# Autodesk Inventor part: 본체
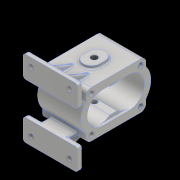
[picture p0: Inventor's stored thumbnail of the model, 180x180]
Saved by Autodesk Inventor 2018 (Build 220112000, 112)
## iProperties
Created: 2023-06
Part Number: 본체
Material: 알루미늄 6061
Document SubType Name: Modeling
Designer: home
Density: 2.7 g/cm^3
Appearance: 알루미늄 - 평지
Mass: 1268.05 g
Surface Area: 985.393 cm^2
Volume: 469.65 cm^3
Author: home
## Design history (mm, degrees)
sketch "스케치1"
  geometry: L1 (-50, 70)-(50, 70); L2 (50, -70)-(-50, -70); L3 (-50, 70)-(50, -70); L4 (50, 70)-(-50, -70); L5 (50, -30)-(-50, -30); L6 (50, 30)-(-50, 30); L7 (50, 70)-(50, 30); L8 (50, -30)-(50, -70); L9 (-50, -70)-(-50, -30); L10 (-50, 30)-(-50, 70); 1 further point
  constraints: 20 end point, 5 parallel, 3 horizontal, 2 midpoint, 2 perpendicular
  dimensions: "d0" = 100 distance of L2.start L2.end; "d1" = 140 distance of L1.end L2.start; "d2" = 40 distance between parallel lines of L1 L6; "d3" = 40 distance between parallel lines of L2 L5; "d4" = 35.5377 deg angle of L7 L3; "d5" = 35.5377 deg angle of L7 L4
extrude "돌출1" new body sketch "스케치1" distance "d6" = 9; taper "d7" = 0 deg
sketch "스케치2"
  geometry: L1 (25, 42.5)-(135, 42.5); L2 (135, 42.5)-(135, -42.5); L3 (135, -42.5)-(25, -42.5); L4 (25, -42.5)-(25, 42.5); L5 (25, 42.5)-(135, -42.5); L6 (135, 42.5)-(25, -42.5); L7 (86.507, 22.5)-(73.493, 22.5); L8 (86.507, -22.5)-(73.493, -22.5); A1 r 40 centre (56, 0) between (25, 25.278) and (25, -25.278); A2 r 40 centre (104, 0) between (135, -25.278) and (135, 25.278); A3 r 28.5 centre (56, 0) between (73.493, 22.5) and (73.493, -22.5); A4 r 28.5 centre (104, 0) between (86.507, -22.5) and (86.507, 22.5); 4 further points
  constraints: 16 end point, 8 point on circle, 4 centre point, 4 midpoint, 4 point on line, 3 horizontal, 2 coincident, 2 equal radius, 2 horizontal alignment, 2 parallel, 1 perpendicular
  dimensions: "d8" = 110 distance of L2.end L3.end; "d9" = 85 distance of L1.end L2.end; "d10" = 80 distance of point (0, 0) point (80, 0); "d17" = 31 distance from line of L4 A1.centre; "d20" = 22.5 distance from line of point (80, 0) L8; "d21" = 22.5 distance from line of point (80, 0) L7; "d119" = 28.5 radius of A4; "d121" = 61.50714 distance from line of L7.end L2; "d122" = 48 distance of A1.centre A2.centre; "d124" = 40 radius of A2
extrude "돌출2" join sketch "스케치2" stored distance "d25" = 79; taper "d26" = 0 deg
fillet "모깎기1" dims "d30" = 5
sketch "스케치4"
  geometry: L1 (-50, -35)-(-50, -65) reference; L2 (-45, -70)-(45, -70) reference; L3 (50, -65)-(50, -35) reference; L4 (45, -30)-(-45, -30) reference; C1 r 9 at (-35, -55); C2 r 9 at (35, -55); C3 r 9 at (-35, 55); C4 r 9 at (35, 55); A1 r 5 centre (-45, -35) between (-45, -30) and (-50, -35) reference; A2 r 5 centre (-45, -65) between (-50, -65) and (-45, -70) reference; A3 r 5 centre (45, -65) between (45, -70) and (50, -65) reference; A4 r 5 centre (45, -35) between (50, -35) and (45, -30) reference; 1 further point
  constraints: 4 centre point, 2 vertical alignment, 1 horizontal alignment
  dimensions: "d31" = 18 diameter of C1; "d32" = 18 diameter of C2; "d33" = 70 distance of C2.centre C1.centre; "d34" = 18 diameter of C3; "d35" = 18 diameter of C4; "d36" = 55 vertical distance of point (0, 0) C1.centre; "d37" = 55 vertical distance of C3.centre point (0, 0); "d38" = 35 horizontal distance of C2.centre point (0, 0); "d39" = 55 vertical distance of point (0, 0) C4.centre
extrude "돌출3" join sketch "스케치4" distance "d40" = 3; taper "d41" = 0 deg
sketch "스케치6"
  geometry: C1 r 9 at (0, 0) reference; C2 r 9 at (70, 0) reference; C3 r 9 at (70, 110) reference; C4 r 9 at (0, 110) reference; 1 further point
hole "구멍1" sketch "스케치6" at (0, 0), (70, 0), (70, 110), (0, 110) diameter "d42" = 9; stored, may be unused: countersink angle "d46" = 90 deg, drill point angle "d48" = 118 deg; dims "d43" = 6, "d44" = 4, "d45" = 2, "d47" = 8
sketch "스케치7"
  geometry: L1 (9, 30)-(25, 30); L2 (25, 38)-(9, 38); L3 (25, 25.278)-(25, 42.5) reference; L4 (25, 38)-(25, 30); L5 (9, 38)-(9, 30); L6 (9, -30)-(9, -35) reference; L7 (9, -30)-(25, -30); L8 (25, -42.5)-(25, -25.278) reference; L9 (25, -38)-(9, -38); L10 (9, -65)-(9, -35) reference; L11 (25, -30)-(25, -38); L12 (9, -30)-(9, -38); 1 further point
  constraints: 16 end point, 5 point on line, 4 horizontal, 1 collinear, 1 perpendicular, 1 vertical
  dimensions: "d49" = 8 distance between parallel lines of L1 L2; "d52" = 8 distance between parallel lines of L9 L7
extrude "돌출4" join sketch "스케치7" stored distance "d50" = 50; taper "d51" = 0 deg
node "작업 평면1"
sketch "스케치8"
  geometry: L1 (9, 62)-(54.939, 42.5); L2 (0, 70)-(9, 70) reference; L3 (9, 64)-(9, 46) reference; L4 (25, 42.5)-(135, 42.5) reference; 1 further point
  constraints: 2 end point, 2 point on line
  dimensions: "d54" = 8 distance from line of L2 L1.start; "d55" = 23 deg angle of L2 L1
feature "리브1" sketch "스케치8" dims "d56" = 1, "d57" = 7, "d58" = 0, "d59" = 0, "d60" = 1, "d61" = 1
fillet "모깎기2" dims "d62" = 10
sketch "스케치9"
  geometry: L1 (22.5, 86.507)-(22.5, 73.493) reference; L2 (-22.5, 73.493)-(-22.5, 86.507) reference; L3 (42.5, 35)-(42.5, 125) reference; L4 (32.5, 135)-(25.278, 135) reference; L5 (-25.278, 135)-(-32.5, 135) reference; L6 (-42.5, 125)-(-42.5, 35) reference; L7 (-32.5, 25)-(-25.278, 25) reference; L8 (25.278, 25)-(32.5, 25) reference; A1 r 28.5 centre (0, 104) between (22.5, 86.507) and (-22.5, 86.507) reference; A2 r 28.5 centre (0, 56) between (-22.5, 73.493) and (22.5, 73.493) reference; A3 r 10 centre (32.5, 35) between (32.5, 25) and (42.5, 35) reference; A4 r 10 centre (32.5, 125) between (42.5, 125) and (32.5, 135) reference; A5 r 40 centre (0, 104) between (25.278, 135) and (-25.278, 135) reference; A6 r 10 centre (-32.5, 125) between (-32.5, 135) and (-42.5, 125) reference; A7 r 10 centre (-32.5, 35) between (-42.5, 35) and (-32.5, 25) reference; A8 r 40 centre (0, 56) between (-25.278, 25) and (25.278, 25) reference; 1 further point
hole "구멍2" sketch "스케치9" at (-32.5, 125), (32.5, 125), (32.5, 35), (-32.5, 35) diameter "d63" = 9; stored, may be unused: countersink angle "d67" = 90 deg, drill point angle "d69" = 118 deg; dims "d64" = 6, "d65" = 4, "d66" = 2, "d68" = 8
sketch "스케치10"
  geometry: L1 (63, -54.939)-(-27, -54.939) reference; L2 (3, 30.061)-(3, 20.061); L3 (33, 20.061)-(33, 30.061); A1 r 15 centre (18, 30.061) between (33, 30.061) and (3, 30.061); A2 r 15 centre (18, 20.061) between (3, 20.061) and (33, 20.061); 1 further point
  constraints: 4 end point, 4 point on circle, 4 tangent, 2 centre point, 1 vertical
  dimensions: "d73" = 30 diameter of A1; "d74" = 30 diameter of A2; "d75" = 30 distance from line of L1.start L3; "d76" = 85 distance from line of L3.end L1; "d77" = 75 distance from line of L3.start L1
extrude "돌출5" join sketch "스케치10" distance "d78" = 5; taper "d79" = 0 deg
sketch "스케치11"
  geometry: L1 (3, 30.061)-(3, 20.061) reference; L2 (33, 20.061)-(33, 30.061) reference; L3 (63, -54.939)-(-27, -54.939) reference; A1 r 15 centre (18, 30.061) between (33, 30.061) and (3, 30.061) reference; A2 r 15 centre (18, 20.061) between (3, 20.061) and (33, 20.061) reference; 3 further points
  constraints: 1 midpoint, 1 vertical alignment
  dimensions: "d81" = 80 distance from line of L3 point (18, 25.061)
hole "구멍3" sketch "스케치11" at (18, 25.061) diameter "d82" = 10.5; stored, may be unused: countersink angle "d88" = 90 deg, drill point angle "d90" = 118 deg; dims "d83" = 11, "d84" = 0.62479, "d85" = 10.589, "d86" = 4, "d87" = 2, "d89" = 30
sketch "스케치17"
  geometry: L1 (22.5, 86.507)-(22.5, 73.493) reference; L2 (-22.5, 73.493)-(-22.5, 86.507) reference; L3 (42.5, 35)-(42.5, 125) reference; L4 (32.5, 135)-(25.278, 135) reference; L5 (-25.278, 135)-(-32.5, 135) reference; L6 (-42.5, 125)-(-42.5, 35) reference; L7 (-32.5, 25)-(-25.278, 25) reference; L8 (25.278, 25)-(32.5, 25) reference; L9 (-28.5, 104)-(28.5, 104); L10 (-28.5, 56)-(28.5, 56); L11 (-28.5, 104)-(-28.5, 56); L12 (28.5, 104)-(28.5, 56); L13 (-59.69, 80)-(78.774, 80); C1 r 4.5 at (32.5, 35) reference; C2 r 4.5 at (-32.5, 125) reference; C3 r 4.5 at (32.5, 125) reference; C4 r 4.5 at (-32.5, 35) reference; A1 r 28.5 centre (0, 104) between (22.5, 86.507) and (-22.5, 86.507) reference; A2 r 28.5 centre (0, 56) between (-22.5, 73.493) and (22.5, 73.493) reference; A3 r 10 centre (32.5, 35) between (32.5, 25) and (42.5, 35) reference; A4 r 10 centre (32.5, 125) between (42.5, 125) and (32.5, 135) reference; A5 r 40 centre (0, 104) between (25.278, 135) and (-25.278, 135) reference; A6 r 10 centre (-32.5, 125) between (-32.5, 135) and (-42.5, 125) reference; A7 r 10 centre (-32.5, 35) between (-42.5, 35) and (-32.5, 25) reference; A8 r 40 centre (0, 56) between (-25.278, 25) and (25.278, 25) reference; A9 r 28.5 centre (0, 104) between (22.5, 86.507) and (-22.5, 86.507) reference; A10 r 28.5 centre (0, 56) between (-22.5, 73.493) and (22.5, 73.493) reference; 1 further point
  constraints: 10 end point, 4 point on circle, 3 horizontal, 2 tangent
  dimensions: "d128" = 80 distance from line of point (0, 0) L13; "d129" = 36.27421 distance from line of L13.end L3; "d130" = 102.1901 distance from line of L13.start L3
extrude "돌출8" cut sketch "스케치17" distance "d106" = 4.5; taper "d107" = 0 deg
fillet "모깎기4" dims "d108" = 3
fillet "모깎기5" dims "d109" = 3
fillet "모깎기6" dims "d110" = 3
fillet "모깎기7" dims "d111" = 3
fillet "모깎기8" dims "d112" = 3
fillet "모깎기9" dims "d113" = 3
fillet "모깎기10" dims "d114" = 3
node "작업 평면3"
sketch "스케치19"
  geometry: 2 further points
  constraints: 1 horizontal alignment, 1 other
  dimensions: "d125" = 20 distance of point (0, 0) point (-20, 0)
feature "엠보싱2" sketch "스케치19" dims "d0" = 100, "d1" = 140, "d2" = 40, "d3" = 40, "d4" = 6.20249, "d5" = 6.20249, "d126" = 0.5, "d127" = 0
node "솔리드1"
mirror "미러1"
mirror "미러2"
mirror "미러3"
mirror "미러4"
node "투영된 루프1"
node "투영된 루프2"
node "투영된 루프3"
node "투영된 루프4"
node "투영된 루프5"
node "투영된 루프6"
node "투영된 루프7"
node "투영된 루프10"
other parameters: "d18" = 57, "d19" = 57, "d53" = 14.5, "d103" = 48, "d104" = 24, "d123" = 144
